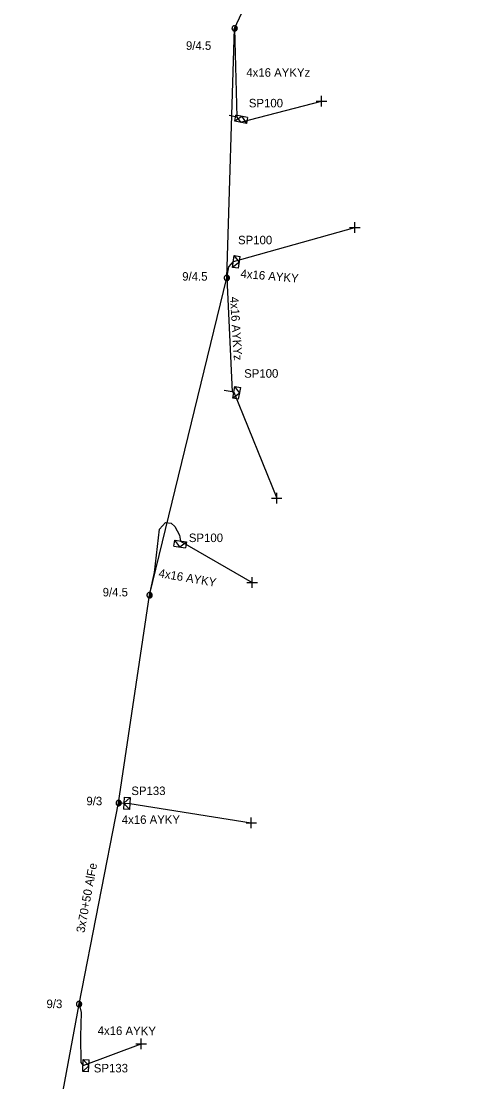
# Model space of a CAD drawing. Extents: x -717562 to -713845, y -1151196 to -1143903.
# Drawn here: x -717137.3 to -717084.3, y -1144215.2 to -1144090.6 of the extents above; entities that cross this region are included whole.
import ezdxf

# ---------------------------------------------------------------- set-up
doc = ezdxf.new("R2010")
doc.units = 0
for name, color, linetype in [('Vrstva 1', 7, 'Continuous'), ('Vrstva 12', 7, 'Continuous'), ('Vrstva 13', 7, 'Continuous'), ('Vrstva 2', 7, 'Continuous'), ('Vrstva 31', 7, 'Continuous'), ('Vrstva 33', 7, 'Continuous'), ('Vrstva 34', 7, 'Continuous'), ('Vrstva 52', 7, 'Continuous'), ('Vrstva 54', 7, 'Continuous'), ('Vrstva 55', 7, 'Continuous'), ('Vrstva 59', 7, 'Continuous'), ('Vrstva 9', 7, 'Continuous')]:
    doc.layers.add(name, color=color, linetype=linetype)

# ---------------------------------------------------------------- blocks, each defined once
blk = doc.blocks.new('NN440')
at = {"layer": 'Vrstva 2'}
for points in [[(0.63, 0), (0.63, 0.06), (0.62, 0.13), (0.6, 0.19), (0.58, 0.25), (0.55, 0.31), (0.51, 0.37), (0.47, 0.42), (0.42, 0.46), (0.37, 0.51), (0.32, 0.54), (0.26, 0.57), (0.2, 0.59), (0.13, 0.61), (0.07, 0.62), (0, 0.63), (-0.06, 0.62), (-0.13, 0.61), (-0.19, 0.59), (-0.26, 0.57), (-0.31, 0.54), (-0.37, 0.51), (-0.42, 0.46), (-0.47, 0.42), (-0.51, 0.37), (-0.54, 0.31), (-0.57, 0.25), (-0.6, 0.19), (-0.62, 0.13), (-0.63, 0.06), (-0.63, 0), (-0.63, -0.07), (-0.62, -0.14), (-0.6, -0.2), (-0.57, -0.26), (-0.54, -0.32), (-0.51, -0.37), (-0.47, -0.43), (-0.42, -0.47), (-0.37, -0.51), (-0.31, -0.55), (-0.26, -0.58), (-0.19, -0.6), (-0.13, -0.62), (-0.06, -0.63), (0, -0.63), (0.07, -0.63), (0.13, -0.62), (0.2, -0.6), (0.26, -0.58), (0.32, -0.55), (0.37, -0.51), (0.42, -0.47), (0.47, -0.43), (0.51, -0.37), (0.55, -0.32), (0.58, -0.26), (0.6, -0.2), (0.62, -0.14), (0.63, -0.07), (0.63, 0)], [(-0.63, 0), (0.63, 0)], [(-0.6, -0.18), (0.57, -0.18)], [(-0.51, -0.32), (0.5, -0.32)], [(-0.37, -0.47), (0.35, -0.47)]]:
    blk.add_lwpolyline(points, dxfattribs=at)
blk = doc.blocks.new('NN800')
at = {"layer": 'Vrstva 1'}
for points in [[(-0.44, 0.44), (0.44, -0.44)], [(-0.44, -0.44), (0.44, 0.44)]]:
    blk.add_lwpolyline(points, dxfattribs=at)
blk = doc.blocks.new('NN630')
at = {"layer": 'Vrstva 9'}
for points in [[(0, -0.7), (-0.7, 0)], [(-0.7, -0.7), (-0.7, 0), (0.7, 0), (0.7, -0.7)], [(-0.7, -0.7), (0.7, -0.7)], [(0, -0.7), (0.7, 0)]]:
    blk.add_lwpolyline(points, dxfattribs=at)
blk = doc.blocks.new('NN510')
at = {"layer": 'Vrstva 2'}
blk.add_lwpolyline([(0, 0), (0, 0.94)], dxfattribs=at)

msp = doc.modelspace()

# ---------------------------------------------------------------- linework, layer by layer
at = {"layer": 'Vrstva 1'}
msp.add_lwpolyline([(-717137.33, -1144242.83), (-717130.54, -1144206.05), (-717125.88, -1144182.43), (-717122.25, -1144158.03), (-717113.17, -1144120.77), (-717112.25, -1144091.46), (-717102.3, -1144070.18), (-717095.42, -1144054.44), (-717084.26, -1144032.61)], dxfattribs=at)
at = {"layer": 'Vrstva 52'}
for points in [[(-717113.17, -1144120.77), (-717112.95, -1144119.46), (-717112.39, -1144118.84)], [(-717122.25, -1144158.03), (-717121.67, -1144155.36), (-717121.1, -1144150.29), (-717120.39, -1144149.48), (-717119.71, -1144149.56), (-717119.26, -1144149.97), (-717118.74, -1144150.96), (-717118.6, -1144151.67)], [(-717125.88, -1144182.43), (-717124.57, -1144182.5)], [(-717130.54, -1144206.05), (-717130.29, -1144207.02), (-717130.37, -1144209.86), (-717130.34, -1144212.91), (-717130.07, -1144213.27)]]:
    msp.add_lwpolyline(points, dxfattribs=at)
at = {"layer": 'Vrstva 54'}
for points in [[(-717112.25, -1144091.46), (-717111.98, -1144101.91), (-717111.55, -1144102.49)], [(-717113.17, -1144120.77), (-717112.54, -1144134.15), (-717112.34, -1144134.19)]]:
    msp.add_lwpolyline(points, dxfattribs=at)
at = {"layer": 'Vrstva 59'}
for points in [[(-717111.55, -1144102.49), (-717102.05, -1144100)], [(-717112.39, -1144118.84), (-717098.12, -1144114.86)], [(-717112.34, -1144134.19), (-717107.31, -1144146.63)], [(-717118.6, -1144151.67), (-717110.18, -1144156.53)], [(-717124.57, -1144182.5), (-717110.29, -1144184.76)], [(-717130.07, -1144213.27), (-717123.23, -1144210.72)]]:
    msp.add_lwpolyline(points, dxfattribs=at)

# ---------------------------------------------------------------- block references
at = {"layer": 'Vrstva 13', "yscale": 0.5}
for p, xscale, rotation in [((-717112.25, -1144091.46), 0.5, 67.79133614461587), ((-717113.17, -1144120.77), 0.5, 77.20851674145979), ((-717122.25, -1144158.03), 0.5, 77.20851664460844), ((-717125.88, -1144182.43), 0.5, 79.59289167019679), ((-717130.54, -1144206.05), 0.5000000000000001, 78.09896664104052)]:
    msp.add_blockref('NN440', p, dxfattribs=dict(at, xscale=xscale, rotation=rotation))
at = {"layer": 'Vrstva 13'}
for p, rotation in [((-717111.98, -1144101.91), 77.73915273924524), ((-717112.54, -1144134.15), 79.17807773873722)]:
    msp.add_blockref('NN510', p, dxfattribs=dict(at, rotation=rotation))
at = {"layer": 'Vrstva 31'}
for p, rotation in [((-717111.55, -1144102.49), 168.98193269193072), ((-717112.39, -1144118.84), 82.1266417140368), ((-717112.34, -1144134.19), 79.17807780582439), ((-717118.6, -1144151.67), -8.375619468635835), ((-717124.57, -1144182.5), -93.67686708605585), ((-717130.07, -1144213.27), 87.18130837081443)]:
    msp.add_blockref('NN630', p, dxfattribs=dict(at, rotation=rotation))
at = {"layer": 'Vrstva 34'}
for p, rotation in [((-717102.05, -1144100), 44.99999995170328), ((-717098.12, -1144114.86), 45), ((-717107.31, -1144146.63), 45), ((-717110.18, -1144156.53), 45), ((-717110.29, -1144184.76), 44.99999995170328), ((-717123.23, -1144210.72), 45)]:
    msp.add_blockref('NN800', p, dxfattribs=dict(at, rotation=rotation))

# ---------------------------------------------------------------- texts
at = {"layer": 'Vrstva 12'}
for s, p in [('9/4.5', (-717117.97, -1144093.98)), ('9/4.5', (-717118.41, -1144121.09)), ('9/4.5', (-717127.76, -1144158.17)), ('9/3', (-717129.67, -1144182.7)), ('9/3', (-717134.36, -1144206.52))]:
    msp.add_text(s, height=1, dxfattribs=at).set_placement(p)
at = {"layer": 'Vrstva 2'}
msp.add_text('3x70+50 AlFe', height=1, rotation=79.593, dxfattribs=at).set_placement((-717129.9, -1144197.73))
at = {"layer": 'Vrstva 33'}
for s, p in [('SP100', (-717110.58, -1144100.74)), ('SP100', (-717111.85, -1144116.82)), ('SP100', (-717111.13, -1144132.49)), ('SP100', (-717117.63, -1144151.79)), ('SP133', (-717124.39, -1144181.5)), ('SP133', (-717128.8, -1144214.07))]:
    msp.add_text(s, height=1, dxfattribs=at).set_placement(p)
at = {"layer": 'Vrstva 54'}
for rotation, p in [(355.053, (-717111.59, -1144120.74)), (350.361, (-717121.24, -1144155.9)), (0.026, (-717125.51, -1144184.88)), (359.439, (-717128.35, -1144209.65))]:
    msp.add_text('4x16 AYKY', height=1, rotation=rotation, dxfattribs=at).set_placement(p)
at = {"layer": 'Vrstva 55'}
for rotation, p in [(359.924, (-717110.88, -1144097.14)), (273.631, (-717112.8, -1144123.01))]:
    msp.add_text('4x16 AYKYz', height=1, rotation=rotation, dxfattribs=at).set_placement(p)

doc.saveas('drawing.dxf')
